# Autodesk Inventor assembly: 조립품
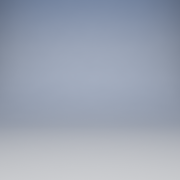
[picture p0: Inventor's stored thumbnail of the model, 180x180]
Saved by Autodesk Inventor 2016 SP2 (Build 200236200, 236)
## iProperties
Created: 2017-08
Part Number: 조립품
Document SubType Name: Assembly
Designer: Administrator
Author: Administrator
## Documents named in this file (1)
- D:\470807V1022\조립품.iam
